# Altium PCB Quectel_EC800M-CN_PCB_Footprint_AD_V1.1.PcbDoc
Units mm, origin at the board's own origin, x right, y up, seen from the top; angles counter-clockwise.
Board outline 152.4 x 101.6 mm, 2 copper layers (Top, Bottom), stack 0.323 mm thick; 1 components, 0 nets, 109 pads, 0 vias.
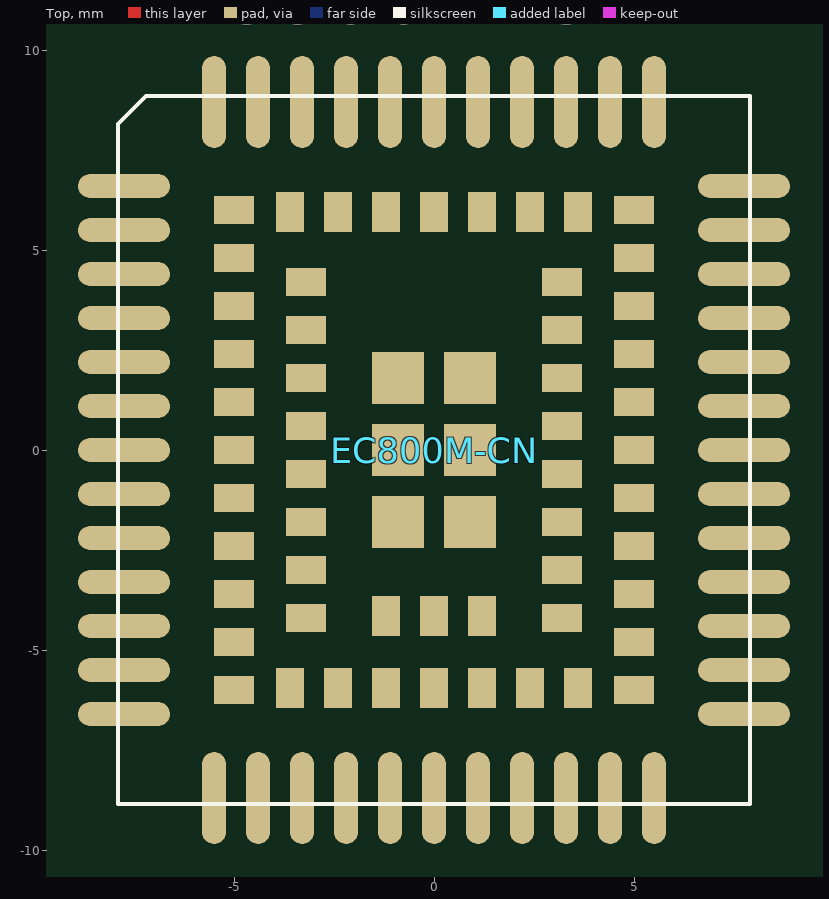
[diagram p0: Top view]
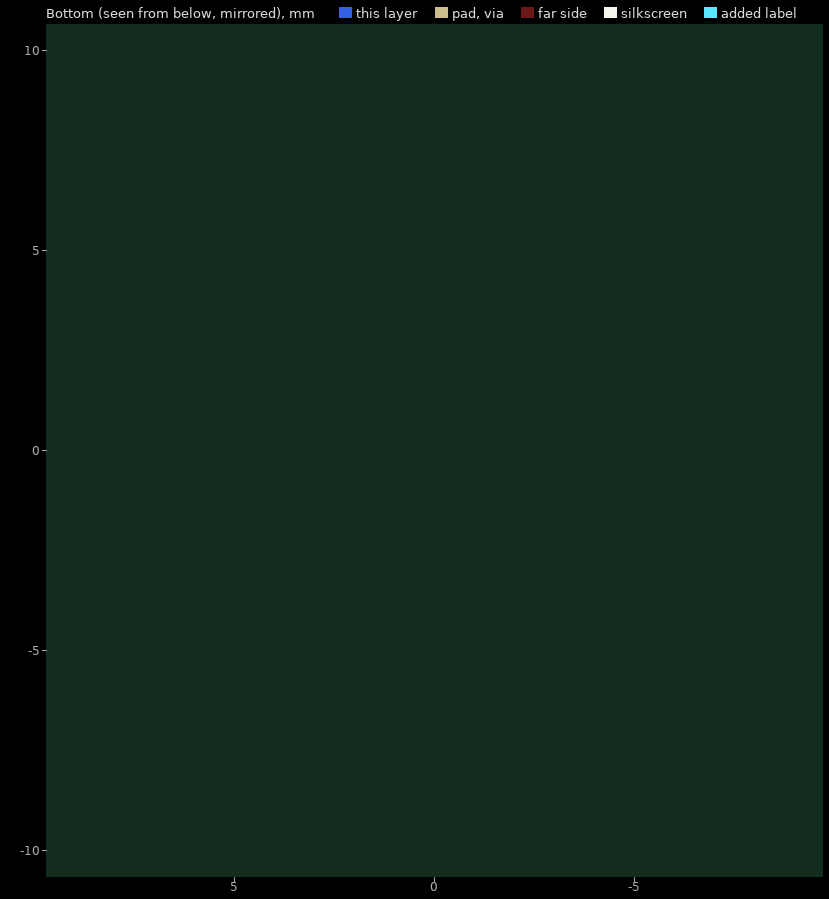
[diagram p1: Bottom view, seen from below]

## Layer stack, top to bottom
Solder Mask Top: solder mask 0.0102, Solder Resist, Dk 3.5
Top: signal copper 0.0343
Dielectric 1: dielectric 0.254, FR-4, Dk 4.3
Bottom: signal copper 0.0343
Solder Mask Bottom: solder mask 0.0102, Solder Resist, Dk 3.5

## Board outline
-78.105,-53.086 74.295,-53.086 74.295,48.514 -78.105,48.514

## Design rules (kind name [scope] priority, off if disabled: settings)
Clearance "Clearance - Default - DEFAULT- SMD" [IsVia vs IsSMTPin] p1: gap=0.152
Clearance "Clearance - Default - DEFAULT - Via" [IsVia vs IsVia] p2: gap=0.152
Clearance "Clearance - Default - DEFAULT - Net" [All] p3: gap=0.152 except(0.254: Text-Text)
ComponentClearance "ComponentClearance - Default - DEFAULT" [All] p1: gap=0.152 collisioncheckmode=3 verticalgap=0.254 showdistances=FALSE
FanoutControl Fanout_Small [(CompPinCount < 5)] p3: bgadir=Out bgaviamode=Centered fanoutstyle=Auto fanoutdirection=OutThenIn viagrid=0.025 // Fanout_Small (Default Rule)
FanoutControl Fanout_SOIC [IsSOIC] p4: bgadir=Out bgaviamode=Centered fanoutstyle=Auto fanoutdirection=Alternating viagrid=0.025 // Fanout_SOIC (Default Rule)
HoleToHoleClearance "HoleToHoleClearance - Default - DEFAULT" [All] p1: gap=0.152 allowstackedmicrovias=TRUE
Length "Default Length" [All] p1: maxlimit=1270 minlimit=0
MaxMinImpedance "Default Impedance" [All] p1: minimum=50.00 maximum=150.0
ParallelSegment "Default Parallel Segment Adjasent" [All] p1: limit=25.4 gap=5.08
ParallelSegment "Default Parallel Segment Same Layer" [All] p2: limit=25.4 gap=5.08
PlaneConnect "Default PlaneConnect" [All] p1: planeconnectstyle=Relief reliefexpansion=0.508 reliefentries=4 reliefconductorwidth=0.381 reliefairgap=0.254
PolygonConnect "PolygonConnect - Default SMT" [IsSMTPin] p1: connectstyle=Relief reliefconductorwidth=0.254 reliefentries=4 polygonreliefangle="45 Angle" airgapwidth=0.254
PolygonConnect "PolygonConnect - Default Pad" [All] p2: connectstyle=Relief reliefconductorwidth=0.381 reliefentries=4 polygonreliefangle="45 Angle" airgapwidth=0.254
RoutingLayers "RoutingLayers - Default - DEFAULT" [All] p1: top layer_v5=TRUE bottom layer_v5=TRUE
RoutingPriority "RoutingPriority - Default - DEFAULT" [All] p1: routingpriority=3
RoutingTopology "Default Routing Topology" [All] p1: topology=Shortest
RoutingVias "RoutingVias - Default - DEFAULT" [All] p1: holewidth=0.94 width=1.397 viastyle="Through Hole" minholewidth=0.94 minwidth=1.397 maxholewidth=0.94 maxwidth=1.397
SMDToCorner "SMDToCorner - Default - DEFAULT" [All] p1: distance=60000
SolderMaskExpansion [All] p1: expansion=0.102
Width "Default Width" [All] p1: maxlimit=0.152 minlimit=0.152 preferedwidth=0.152
22 further rules are at their usual default settings.

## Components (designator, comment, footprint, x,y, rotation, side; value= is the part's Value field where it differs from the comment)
EC800M-CN "Comment" EC800M-CN 0,0 r0 top

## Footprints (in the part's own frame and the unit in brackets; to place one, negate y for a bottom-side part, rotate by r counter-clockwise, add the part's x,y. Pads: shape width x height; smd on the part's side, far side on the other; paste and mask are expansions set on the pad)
EC800M-CN [mm] "EC800M-CN Moudle 109PIN 15.8X17.7mm H2.4mm RO"
  oval 2.3x0.6 smd mask+0.05: 1(-7.75,6.6) 2(-7.75,5.5) 3(-7.75,4.4) 4(-7.75,3.3) 5(-7.75,2.2) 6(-7.75,1.1) 7(-7.75,0) 8(-7.75,-1.1) 9(-7.75,-2.2) 10(-7.75,-3.3) 11(-7.75,-4.4) 12(-7.75,-5.5) 13(-7.75,-6.6) 23(7.75,-6.6) 24(7.75,-5.5) 25(7.75,-4.4) 26(7.75,-3.3) 27(7.75,-2.2) 28(7.75,-1.1) 29(7.75,0) 30(7.75,1.1) 31(7.75,2.2) 32(7.75,3.3) 33(7.75,4.4) 34(7.75,5.5) 35(7.75,6.6)
  oval 0.6x2.3 smd mask+0.05: 14(-4.4,-8.7) 15(-3.3,-8.7) 16(-2.2,-8.7) 17(-1.1,-8.7) 18(0,-8.7) 19(1.1,-8.7) 20(2.2,-8.7) 21(3.3,-8.7) 22(4.4,-8.7) 36(4.4,8.7) 37(3.3,8.7) 38(2.2,8.7) 39(1.1,8.7) 40(0,8.7) 41(-1.1,8.7) 42(-2.2,8.7) 43(-3.3,8.7) 44(-4.4,8.7) 95(-5.5,-8.7) 96(5.5,-8.7) 97(5.5,8.7) 98(-5.5,8.7)
  rect 1x0.7 smd mask+0.05: 45(-5,4.8) 46(-5,3.6) 47(-5,2.4) 48(-5,1.2) 49(-5,0) 50(-5,-1.2) 51(-5,-2.4) 52(-5,-3.6) 53(-5,-4.8) 59(5,-4.8) 60(5,-3.6) 61(5,-2.4) 62(5,-1.2) 63(5,0) 64(5,1.2) 65(5,2.4) 66(5,3.6) 67(5,4.8) 73(-3.2,4.2) 74(-3.2,3) 75(-3.2,1.8) 76(-3.2,0.6) 77(-3.2,-0.6) 78(-3.2,-1.8) 79(-3.2,-3) 80(-3.2,-4.2) 81(3.2,-4.2) 82(3.2,-3) 83(3.2,-1.8) 84(3.2,-0.6) 85(3.2,0.6) 86(3.2,1.8) 87(3.2,3) 88(3.2,4.2) 99(-5,6) 100(-5,-6) 103(5,-6) 104(5,6)
  rect 0.7x1 smd mask+0.05: 54(-2.4,-5.95) 55(-1.2,-5.95) 56(0,-5.95) 57(1.2,-5.95) 58(2.4,-5.95) 68(2.4,5.95) 69(1.2,5.95) 70(0,5.95) 71(-1.2,5.95) 72(-2.4,5.95) 101(-3.6,-5.95) 102(3.6,-5.95) 105(3.6,5.95) 106(-3.6,5.95) 107(-1.2,-4.15) 108(0,-4.15) 109(1.2,-4.15)
  rect 1.3x1.3 smd mask+0.05: 89(-0.9,1.8) 90(-0.9,0) 91(-0.9,-1.8) 92(0.9,-1.8) 93(0.9,0) 94(0.9,1.8)
  silkscreen extent -7.9,-8.85 7.9,8.85

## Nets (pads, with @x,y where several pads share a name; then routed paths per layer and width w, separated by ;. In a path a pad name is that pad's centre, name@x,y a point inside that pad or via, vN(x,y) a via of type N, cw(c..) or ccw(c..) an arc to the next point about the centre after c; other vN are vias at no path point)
pads on no net: EC800M-CN.1 EC800M-CN.2 EC800M-CN.3 EC800M-CN.4 EC800M-CN.5 EC800M-CN.6 EC800M-CN.7 EC800M-CN.8 EC800M-CN.9 EC800M-CN.10 EC800M-CN.11 EC800M-CN.12 EC800M-CN.13 EC800M-CN.14 EC800M-CN.15 EC800M-CN.16 EC800M-CN.17 EC800M-CN.18 EC800M-CN.19 EC800M-CN.20 EC800M-CN.21 EC800M-CN.22 EC800M-CN.23 EC800M-CN.24 EC800M-CN.25 EC800M-CN.26 EC800M-CN.27 EC800M-CN.28 EC800M-CN.29 EC800M-CN.30 EC800M-CN.31 EC800M-CN.32 EC800M-CN.33 EC800M-CN.34 EC800M-CN.35 EC800M-CN.36 EC800M-CN.37 EC800M-CN.38 EC800M-CN.39 EC800M-CN.40 EC800M-CN.41 EC800M-CN.42 EC800M-CN.43 EC800M-CN.44 EC800M-CN.45 EC800M-CN.46 EC800M-CN.47 EC800M-CN.48 EC800M-CN.49 EC800M-CN.50 EC800M-CN.51 EC800M-CN.52 EC800M-CN.53 EC800M-CN.54 EC800M-CN.55 EC800M-CN.56 EC800M-CN.57 EC800M-CN.58 EC800M-CN.59 EC800M-CN.60 EC800M-CN.61 EC800M-CN.62 EC800M-CN.63 EC800M-CN.64 EC800M-CN.65 EC800M-CN.66 EC800M-CN.67 EC800M-CN.68 EC800M-CN.69 EC800M-CN.70 EC800M-CN.71 EC800M-CN.72 EC800M-CN.73 EC800M-CN.74 EC800M-CN.75 EC800M-CN.76 EC800M-CN.77 EC800M-CN.78 EC800M-CN.79 EC800M-CN.80 EC800M-CN.81 EC800M-CN.82 EC800M-CN.83 EC800M-CN.84 EC800M-CN.85 EC800M-CN.86 EC800M-CN.87 EC800M-CN.88 EC800M-CN.89 EC800M-CN.90 EC800M-CN.91 EC800M-CN.92 EC800M-CN.93 EC800M-CN.94 EC800M-CN.95 EC800M-CN.96 EC800M-CN.97 EC800M-CN.98 EC800M-CN.99 EC800M-CN.100 EC800M-CN.101 EC800M-CN.102 EC800M-CN.103 EC800M-CN.104 EC800M-CN.105 EC800M-CN.106 EC800M-CN.107 EC800M-CN.108 EC800M-CN.109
